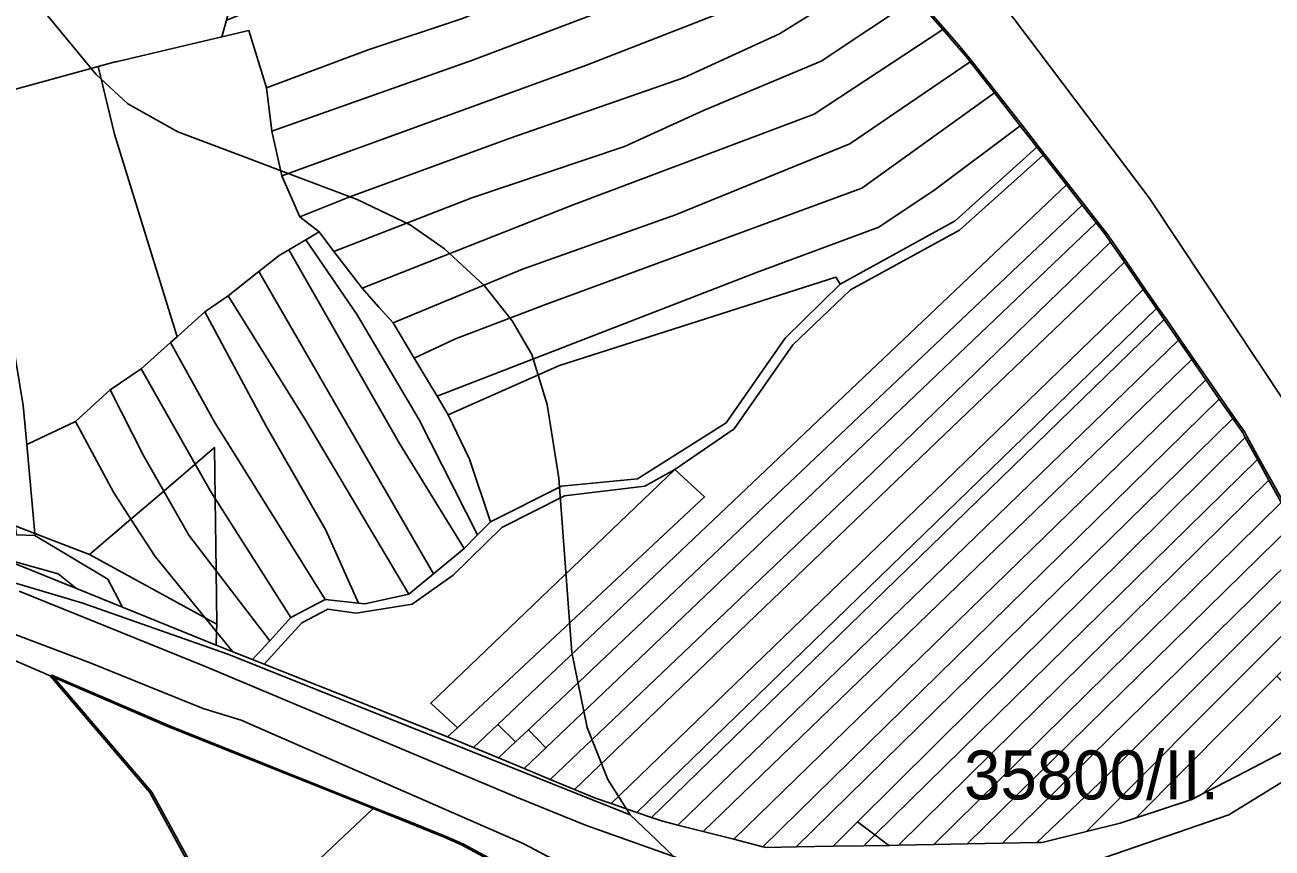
# Model space of a CAD drawing. Extents: x -535894 to -532827, y -1165802 to -1163635.
# Drawn here: x -533561 to -533178.9, y -1164904.6 to -1164652.6 of the extents above; entities that cross this region are included whole.
import ezdxf

# ---------------------------------------------------------------- set-up
doc = ezdxf.new("R2010")
doc.units = 0
for name, color, linetype in [('BPEJ_s', 7, 'Continuous'), ('orna_s', 7, 'Continuous'), ('ostatni_s', 7, 'Continuous'), ('PUPFL_s', 7, 'Continuous'), ('sad_s', 7, 'Continuous'), ('voda_s', 7, 'Continuous')]:
    doc.layers.add(name, color=color, linetype=linetype)

msp = doc.modelspace()

# ---------------------------------------------------------------- linework, layer by layer
at = {"layer": 'BPEJ_s'}
for points in [[(-533420.14, -1164732.49), (-533432.41, -1164721.18), (-533442.921, -1164713.859), (-533459.171, -1164706.05), (-533481.15, -1164697.769), (-533495.14, -1164692.5), (-533497.619, -1164691.566), (-533514.087, -1164685.362), (-533529.464, -1164676.803), (-533539.13, -1164667.83), (-533562.86, -1164639), (-533582.853, -1164607.463), (-533591.21, -1164585.32), (-533601.72, -1164540.56), (-533606.34, -1164507.75), (-533606.98, -1164481.63)], [(-533562.86, -1164639), (-533539.13, -1164667.83), (-533529.464, -1164676.803), (-533514.087, -1164685.362), (-533497.619, -1164691.566), (-533495.14, -1164692.5), (-533481.15, -1164697.769), (-533459.171, -1164706.05), (-533442.921, -1164713.859), (-533432.41, -1164721.18), (-533420.14, -1164732.49), (-533411.7, -1164743.171), (-533405.65, -1164753.52), (-533401.03, -1164768.81), (-533397.377, -1164791.431), (-533395.133, -1164821.465), (-533393.39, -1164844.791), (-533388.77, -1164867.72), (-533382.4, -1164883.65), (-533375.59, -1164894.45), (-533394.048, -1164887.08), (-533403.749, -1164883.207), (-533424.899, -1164874.762), (-533457.69, -1164861.67), (-533467.869, -1164857.606), (-533498.791, -1164845.26), (-533540.07, -1164830.759), (-533543.229, -1164829.65), (-533582.452, -1164818)], [(-533287.544, -1164644.206), (-533279.194, -1164653.887), (-533275.013, -1164658.729), (-533272.072, -1164662.135), (-533270.5, -1164664.24), (-533263.368, -1164673.254), (-533255.52, -1164683.292), (-533250.35, -1164689.904), (-533248.429, -1164692.351), (-533241.312, -1164701.443), (-533236.475, -1164707.625), (-533232.221, -1164713.068), (-533229.587, -1164716.44), (-533227.835, -1164718.959), (-533223.56, -1164725.119), (-533217.768, -1164733.469), (-533213.763, -1164739.247), (-533211.404, -1164742.648), (-533206.99, -1164749.005), (-533202.897, -1164754.903), (-533198.613, -1164761.074), (-533194.476, -1164767.027), (-533190.332, -1164773.001), (-533187.314, -1164777.351), (-533186.536, -1164778.766), (-533182.834, -1164785.465), (-533179.324, -1164791.812), (-533175.539, -1164798.672)], [(-533186.536, -1164778.766), (-533187.314, -1164777.351), (-533190.332, -1164773.001), (-533194.476, -1164767.027), (-533198.613, -1164761.074), (-533202.897, -1164754.903), (-533206.99, -1164749.005), (-533211.404, -1164742.648), (-533213.763, -1164739.247), (-533217.768, -1164733.469), (-533223.56, -1164725.119), (-533227.835, -1164718.959), (-533229.587, -1164716.44), (-533232.221, -1164713.068), (-533236.475, -1164707.625), (-533241.312, -1164701.443), (-533248.429, -1164692.351), (-533250.35, -1164689.904), (-533255.52, -1164683.292), (-533263.368, -1164673.254), (-533270.5, -1164664.24), (-533272.072, -1164662.135), (-533275.013, -1164658.729), (-533279.194, -1164653.887), (-533287.544, -1164644.206)], [(-533356.59, -1164912.8), (-533367.42, -1164902.28), (-533375.59, -1164894.45), (-533382.4, -1164883.65), (-533388.77, -1164867.72), (-533393.39, -1164844.791), (-533395.133, -1164821.465), (-533397.377, -1164791.431), (-533401.03, -1164768.81), (-533405.65, -1164753.52), (-533411.7, -1164743.171), (-533420.14, -1164732.49)], [(-533175.539, -1164798.672), (-533179.324, -1164791.812), (-533182.834, -1164785.465), (-533186.536, -1164778.766)], [(-533582.452, -1164818), (-533543.229, -1164829.65), (-533540.07, -1164830.759), (-533498.791, -1164845.26), (-533467.869, -1164857.606), (-533457.69, -1164861.67), (-533424.899, -1164874.762), (-533403.749, -1164883.207), (-533394.048, -1164887.08), (-533375.59, -1164894.45)], [(-533382.308, -1164927.394), (-533426.603, -1164903.475), (-533431.702, -1164901.198), (-533444.833, -1164895.95), (-533453.712, -1164892.401), (-533516.384, -1164867.359), (-533552.673, -1164851.701), (-533522.095, -1164887.508), (-533497.114, -1164933.287)], [(-533497.114, -1164933.287), (-533522.095, -1164887.508), (-533552.673, -1164851.701), (-533516.384, -1164867.359), (-533453.712, -1164892.401), (-533444.833, -1164895.95), (-533431.702, -1164901.198), (-533426.603, -1164903.475), (-533382.308, -1164927.394)], [(-533375.59, -1164894.45), (-533367.42, -1164902.28), (-533356.59, -1164912.8)]]:
    msp.add_lwpolyline(points, dxfattribs=at)
at = {"layer": 'orna_s'}
for points in [[(-533340.54, -1164585.66), (-533339.13, -1164587.05), (-533322.44, -1164605.61), (-533347.58, -1164619.33), (-533427.18, -1164650.69), (-533455.83, -1164660.22), (-533487.01, -1164671.82), (-533492.36, -1164654.31), (-533500.62, -1164656.25), (-533499.25, -1164651.17), (-533494.36, -1164649.22), (-533406.4, -1164614.18), (-533358.81, -1164596.53)], [(-533322.44, -1164605.61), (-533313.54, -1164615.51), (-533338.15, -1164629.18), (-533377.68, -1164645.97), (-533423.57, -1164663.33), (-533485.32, -1164685.09), (-533487.01, -1164671.82), (-533455.83, -1164660.22), (-533427.18, -1164650.69), (-533347.58, -1164619.33)], [(-533313.54, -1164615.51), (-533304.78, -1164625.25), (-533334.44, -1164643.61), (-533388.98, -1164664.88), (-533482.26, -1164698.81), (-533485.32, -1164685.09), (-533423.57, -1164663.33), (-533377.68, -1164645.97), (-533338.15, -1164629.18)], [(-533304.78, -1164625.25), (-533301.29, -1164629.13), (-533296.52, -1164634.66), (-533329.78, -1164655.32), (-533359.19, -1164668.82), (-533412.28, -1164687.27), (-533461.47, -1164705.24), (-533476.71, -1164711.39), (-533482.26, -1164698.81), (-533388.98, -1164664.88), (-533334.44, -1164643.61)], [(-533288.14, -1164644.37), (-533317.08, -1164663.67), (-533353.14, -1164678.82), (-533377.32, -1164689.81), (-533424.1, -1164705.54), (-533466.29, -1164721.94), (-533470.86, -1164715.95), (-533476.71, -1164711.39), (-533461.47, -1164705.24), (-533412.28, -1164687.27), (-533359.19, -1164668.82), (-533329.78, -1164655.32), (-533296.52, -1164634.66)], [(-533279.79, -1164654.05), (-533319.2, -1164679.92), (-533393, -1164707.69), (-533457.69, -1164733.24), (-533466.29, -1164721.94), (-533424.1, -1164705.54), (-533377.32, -1164689.81), (-533353.14, -1164678.82), (-533317.08, -1164663.67), (-533288.14, -1164644.37)], [(-533492.36, -1164654.31), (-533487.01, -1164671.82), (-533485.32, -1164685.09), (-533482.26, -1164698.81), (-533476.71, -1164711.39), (-533470.86, -1164715.95), (-533474.96, -1164718.4), (-533480.08, -1164721.45), (-533483.04, -1164723.22), (-533489.28, -1164728.14), (-533498.69, -1164735.57), (-533505.89, -1164740.44), (-533510.96, -1164745.02), (-533514.36, -1164748.08), (-533533.54, -1164686.07), (-533538.54, -1164665.37), (-533533.28, -1164663.93), (-533533.01, -1164663.86), (-533500.62, -1164656.25)], [(-533275.61, -1164658.9), (-533272.67, -1164662.3), (-533271.44, -1164663.87), (-533308.24, -1164688.97), (-533361.65, -1164710.75), (-533408.54, -1164727.43), (-533448.21, -1164743.81), (-533452.5, -1164739.03), (-533457.69, -1164733.24), (-533393, -1164707.69), (-533319.2, -1164679.92), (-533279.79, -1164654.05)], [(-533263.96, -1164673.42), (-533304.62, -1164702.63), (-533402.02, -1164738.38), (-533429.04, -1164748.7), (-533441.74, -1164754.6), (-533448.21, -1164743.81), (-533408.54, -1164727.43), (-533361.65, -1164710.75), (-533308.24, -1164688.97), (-533271.44, -1164663.87)], [(-533538.54, -1164665.37), (-533533.54, -1164686.07), (-533514.36, -1164748.08), (-533516.33, -1164749.86), (-533525.31, -1164757.95), (-533534.9, -1164764.3), (-533545.47, -1164773.99), (-533560.4, -1164781.07), (-533561.46, -1164769.12), (-533570.16, -1164717), (-533578.79, -1164676.38)], [(-533256.12, -1164683.46), (-533282.08, -1164703), (-533299.42, -1164714.57), (-533336.81, -1164728.38), (-533434.73, -1164766.3), (-533441.74, -1164754.6), (-533429.04, -1164748.7), (-533402.02, -1164738.38), (-533304.62, -1164702.63), (-533263.96, -1164673.42)], [(-533584.41, -1164677.93), (-533578.79, -1164676.38), (-533570.16, -1164717), (-533561.46, -1164769.12), (-533560.4, -1164781.07), (-533557.97, -1164808.32), (-533563.91, -1164806.02), (-533571.28, -1164756.52)], [(-533250.95, -1164690.07), (-533275.95, -1164712.64), (-533311.18, -1164731.99), (-533311.82, -1164730.97), (-533312.53, -1164729.81), (-533397.17, -1164756.86), (-533431.33, -1164771.97), (-533434.73, -1164766.3), (-533336.81, -1164728.38), (-533299.42, -1164714.57), (-533282.08, -1164703), (-533256.12, -1164683.46)], [(-533249.02, -1164692.52), (-533274.65, -1164715.44), (-533308.05, -1164733.69), (-533325.72, -1164750.58), (-533343.74, -1164776.33), (-533361.85, -1164788.7), (-533371.03, -1164793.86), (-533395.69, -1164796.81), (-533414.89, -1164806.5), (-533429.78, -1164821.14), (-533442.29, -1164829.96), (-533459.47, -1164832.75), (-533468.18, -1164831.46), (-533476.1, -1164835.72), (-533487.68, -1164848.33), (-533491.23, -1164846.91), (-533485.98, -1164841.17), (-533479.52, -1164834.02), (-533469.04, -1164828.56), (-533458.74, -1164829.65), (-533456.82, -1164829.86), (-533443.36, -1164826.95), (-533435.81, -1164820.69), (-533426.45, -1164812.95), (-533422.33, -1164808.76), (-533418.38, -1164804.75), (-533396.57, -1164793.83), (-533373.28, -1164791.61), (-533346.13, -1164774.47), (-533328.04, -1164748.55), (-533311.18, -1164731.99), (-533275.95, -1164712.64), (-533250.95, -1164690.07)], [(-533249.02, -1164692.52), (-533241.91, -1164701.61), (-533416.06, -1164866.8), (-533423.51, -1164873.88), (-533428.43, -1164871.84), (-533431.47, -1164870.62), (-533428.45, -1164867.8), (-533352.76, -1164797.14), (-533361.85, -1164788.7), (-533343.74, -1164776.33), (-533325.72, -1164750.58), (-533308.05, -1164733.69), (-533274.65, -1164715.44)], [(-533237.07, -1164707.79), (-533406.74, -1164868.43), (-533410.69, -1164872.17), (-533416.06, -1164866.8), (-533241.91, -1164701.61)], [(-533232.82, -1164713.23), (-533401.39, -1164873.99), (-533406.74, -1164868.43), (-533237.07, -1164707.79)], [(-533230.18, -1164716.6), (-533228.43, -1164719.12), (-533301.21, -1164789.57), (-533400.11, -1164883.63), (-533408.04, -1164880.32), (-533401.39, -1164873.99), (-533232.82, -1164713.23)], [(-533470.86, -1164715.95), (-533466.29, -1164721.94), (-533457.69, -1164733.24), (-533452.5, -1164739.03), (-533448.21, -1164743.81), (-533441.74, -1164754.6), (-533434.73, -1164766.3), (-533431.33, -1164771.97), (-533424.81, -1164785.55), (-533418.38, -1164804.75), (-533422.33, -1164808.76), (-533440.21, -1164773.49), (-533459.21, -1164741.38), (-533474.96, -1164718.4)], [(-533480.08, -1164721.45), (-533446.26, -1164780.81), (-533426.45, -1164812.95), (-533435.81, -1164820.69), (-533489.28, -1164728.14), (-533483.04, -1164723.22)], [(-533474.96, -1164718.4), (-533459.21, -1164741.38), (-533440.21, -1164773.49), (-533422.33, -1164808.76), (-533426.45, -1164812.95), (-533446.26, -1164780.81), (-533480.08, -1164721.45)], [(-533224.16, -1164725.28), (-533286.57, -1164785.1), (-533392.63, -1164886.74), (-533400.11, -1164883.63), (-533301.21, -1164789.57), (-533228.43, -1164719.12)], [(-533218.37, -1164733.63), (-533279.2, -1164792.37), (-533381.38, -1164891.04), (-533386.52, -1164889.28), (-533392.63, -1164886.74), (-533286.57, -1164785.1), (-533224.16, -1164725.28)], [(-533489.28, -1164728.14), (-533435.81, -1164820.69), (-533443.36, -1164826.95), (-533474.92, -1164773.7), (-533498.69, -1164735.57)], [(-533311.82, -1164730.97), (-533311.18, -1164731.99), (-533328.04, -1164748.55), (-533346.13, -1164774.47), (-533373.28, -1164791.61), (-533396.57, -1164793.83), (-533418.38, -1164804.75), (-533424.81, -1164785.55), (-533431.33, -1164771.97), (-533397.17, -1164756.86), (-533312.53, -1164729.81)], [(-533498.69, -1164735.57), (-533474.92, -1164773.7), (-533443.36, -1164826.95), (-533456.82, -1164829.86), (-533458.74, -1164829.65), (-533468.79, -1164807.32), (-533487.2, -1164775.28), (-533505.89, -1164740.44)], [(-533214.36, -1164739.41), (-533373.49, -1164893.74), (-533381.38, -1164891.04), (-533279.2, -1164792.37), (-533218.37, -1164733.63)], [(-533505.89, -1164740.44), (-533487.2, -1164775.28), (-533468.79, -1164807.32), (-533458.74, -1164829.65), (-533469.04, -1164828.56), (-533497.51, -1164782.8), (-533502.66, -1164774.54), (-533516.33, -1164749.86), (-533514.36, -1164748.08), (-533510.96, -1164745.02)], [(-533212, -1164742.81), (-533369.05, -1164895.26), (-533373.49, -1164893.74), (-533214.36, -1164739.41)], [(-533207.59, -1164749.17), (-533360.93, -1164897.6), (-533365.96, -1164896.32), (-533369.05, -1164895.26), (-533212, -1164742.81)], [(-533516.33, -1164749.86), (-533502.66, -1164774.54), (-533497.51, -1164782.8), (-533469.04, -1164828.56), (-533479.52, -1164834.02), (-533502.68, -1164797.66), (-533502.89, -1164782), (-533508.81, -1164787.07), (-533525.31, -1164757.95)], [(-533203.5, -1164755.07), (-533353.15, -1164899.58), (-533360.93, -1164897.6), (-533207.59, -1164749.17)], [(-533199.21, -1164761.24), (-533343.76, -1164901.98), (-533353.15, -1164899.58), (-533203.5, -1164755.07)], [(-533525.31, -1164757.95), (-533508.81, -1164787.07), (-533518.46, -1164795.33), (-533524.53, -1164784.7), (-533534.9, -1164764.3)], [(-533195.08, -1164767.19), (-533334.89, -1164904.23), (-533343.76, -1164901.98), (-533199.21, -1164761.24)], [(-533534.9, -1164764.3), (-533524.53, -1164784.7), (-533518.46, -1164795.33), (-533528.49, -1164803.93), (-533533.83, -1164795.72), (-533545.47, -1164773.99)], [(-533190.93, -1164773.16), (-533324.7, -1164904.32), (-533333.91, -1164904.48), (-533334.89, -1164904.23), (-533195.08, -1164767.19)], [(-533545.47, -1164773.99), (-533533.83, -1164795.72), (-533528.49, -1164803.93), (-533541.19, -1164814.8), (-533557.97, -1164808.32), (-533560.4, -1164781.07)], [(-533187.91, -1164777.51), (-533187.14, -1164778.93), (-533305.88, -1164896.66), (-533313.39, -1164904.12), (-533324.7, -1164904.32), (-533190.93, -1164773.16)], [(-533183.43, -1164785.63), (-533300.56, -1164900.63), (-533305.88, -1164896.66), (-533187.14, -1164778.93)], [(-533179.93, -1164791.97), (-533293.4, -1164903.76), (-533296.3, -1164903.82), (-533300.56, -1164900.63), (-533183.43, -1164785.63)], [(-533371.03, -1164793.86), (-533361.85, -1164788.7), (-533436.64, -1164860.32), (-533428.45, -1164867.8), (-533431.47, -1164870.62), (-533487.68, -1164848.33), (-533476.1, -1164835.72), (-533468.18, -1164831.46), (-533459.47, -1164832.75), (-533442.29, -1164829.96), (-533429.78, -1164821.14), (-533414.89, -1164806.5), (-533395.69, -1164796.81)], [(-533361.85, -1164788.7), (-533352.76, -1164797.14), (-533428.45, -1164867.8), (-533436.64, -1164860.32)], [(-533176.14, -1164798.83), (-533282.57, -1164903.56), (-533293.4, -1164903.76), (-533179.93, -1164791.97)], [(-533502.68, -1164797.66), (-533479.52, -1164834.02), (-533485.98, -1164841.17), (-533502.38, -1164819.76)], [(-533172.45, -1164805.52), (-533272.33, -1164903.38), (-533282.57, -1164903.56), (-533176.14, -1164798.83)], [(-533168.77, -1164812.17), (-533261.52, -1164903.19), (-533272.33, -1164903.38), (-533172.45, -1164805.52)], [(-533165.34, -1164818.38), (-533229.86, -1164882.85), (-533251.03, -1164902.99), (-533261.52, -1164903.19), (-533168.77, -1164812.17)], [(-533502.38, -1164819.76), (-533485.98, -1164841.17), (-533491.23, -1164846.91), (-533497.24, -1164844.53), (-533502.24, -1164838.41), (-533502.15, -1164836.07)], [(-533163.04, -1164822.52), (-533161.85, -1164825.47), (-533182.9, -1164846.57), (-533235.8, -1164899.62), (-533249.36, -1164902.96), (-533251.03, -1164902.99), (-533229.86, -1164882.85), (-533165.34, -1164818.38)], [(-533158.74, -1164833.17), (-533177.43, -1164852), (-533220.52, -1164895.43), (-533225.42, -1164897.07), (-533235.8, -1164899.62), (-533182.9, -1164846.57), (-533161.85, -1164825.47)], [(-533502.24, -1164838.41), (-533497.24, -1164844.53), (-533502.39, -1164842.48)], [(-533154.75, -1164843.06), (-533166.05, -1164860.58), (-533175.17, -1164875.08), (-533189.49, -1164882.49), (-533200, -1164887.93), (-533192.13, -1164880.06), (-533170.75, -1164858.64), (-533154.89, -1164842.74)], [(-533170.75, -1164858.64), (-533192.13, -1164880.06), (-533200, -1164887.93), (-533203.49, -1164889.74), (-533220.52, -1164895.43), (-533177.43, -1164852)], [(-533410.69, -1164872.17), (-533415.86, -1164877.07), (-533423.51, -1164873.88), (-533416.06, -1164866.8)], [(-533410.69, -1164872.17), (-533406.74, -1164868.43), (-533401.39, -1164873.99), (-533408.04, -1164880.32), (-533415.86, -1164877.07)], [(-533305.88, -1164896.66), (-533300.56, -1164900.63), (-533303.94, -1164903.95), (-533313.39, -1164904.12)], [(-533300.56, -1164900.63), (-533296.3, -1164903.82), (-533303.94, -1164903.95)]]:
    msp.add_lwpolyline(points, close=True, dxfattribs=at)
msp.add_lwpolyline([(-533589.15, -1164642.49), (-533534.45, -1164626.61), (-533502.26, -1164617.26), (-533500.35, -1164622.14), (-533495.05, -1164635.67), (-533499.25, -1164651.17), (-533500.62, -1164656.25), (-533533.01, -1164663.86), (-533533.28, -1164663.93), (-533538.54, -1164665.37), (-533578.79, -1164676.38)], dxfattribs=at)
at = {"layer": 'ostatni_s'}
for points in [[(-533404.17, -1164500.26), (-533365.03, -1164536.67), (-533325.21, -1164575.74), (-533286.88, -1164617.4), (-533258.18, -1164650.51), (-533216.56, -1164705.51), (-533174.44, -1164769.08)], [(-533176.14, -1164798.83), (-533179.93, -1164791.97), (-533183.43, -1164785.63), (-533187.14, -1164778.93), (-533187.91, -1164777.51), (-533190.93, -1164773.16), (-533195.08, -1164767.19), (-533199.21, -1164761.24), (-533203.5, -1164755.07), (-533207.59, -1164749.17), (-533212, -1164742.81), (-533214.36, -1164739.41), (-533218.37, -1164733.63), (-533224.16, -1164725.28), (-533228.43, -1164719.12), (-533230.18, -1164716.6), (-533232.82, -1164713.23), (-533237.07, -1164707.79), (-533241.91, -1164701.61), (-533249.02, -1164692.52), (-533250.95, -1164690.07), (-533256.12, -1164683.46), (-533263.96, -1164673.42), (-533271.44, -1164663.87), (-533272.67, -1164662.3), (-533275.61, -1164658.9), (-533279.79, -1164654.05), (-533288.14, -1164644.37)], [(-533562.74, -1164826), (-533505.42, -1164849.16), (-533410.4, -1164889.02), (-533389.23, -1164897.67), (-533361.33, -1164907.54)], [(-533391.45, -1164912.18), (-533408.38, -1164903.25), (-533494.69, -1164865.48), (-533506.09, -1164862.02), (-533509.4, -1164860.71), (-533541, -1164847.96), (-533589.21, -1164829.81)], [(-533589.21, -1164829.81), (-533541, -1164847.96), (-533509.4, -1164860.71), (-533506.09, -1164862.02), (-533494.69, -1164865.48), (-533408.38, -1164903.25), (-533391.45, -1164912.18)], [(-533369.34, -1164934.9), (-533427.21, -1164903.65), (-533432.31, -1164901.38), (-533454.32, -1164892.58), (-533516.99, -1164867.54), (-533553.28, -1164851.89), (-533596.46, -1164833.25)], [(-533236.41, -1164909.7), (-533192.2, -1164894.47), (-533171.4, -1164881.68), (-533146.9, -1164867.45), (-533132.1, -1164861.81), (-533130.26, -1164863.56), (-533127.47, -1164863.11), (-533123.98, -1164868.64), (-533119.52, -1164875.7), (-533116.52, -1164880.45), (-533127.62, -1164885.63), (-533134.02, -1164888.62), (-533147.32, -1164895.13), (-533230.7, -1164935.9)], [(-533497.72, -1164933.47), (-533454.32, -1164892.58), (-533432.31, -1164901.38), (-533427.21, -1164903.65), (-533369.34, -1164934.9)]]:
    msp.add_lwpolyline(points, dxfattribs=at)
for points in [[(-533508.81, -1164787.07), (-533502.89, -1164782), (-533502.68, -1164797.66), (-533503.83, -1164795.85)], [(-533518.46, -1164795.33), (-533508.81, -1164787.07), (-533503.83, -1164795.85), (-533502.68, -1164797.66), (-533502.38, -1164819.76), (-533510.76, -1164808.8)], [(-533528.49, -1164803.93), (-533518.46, -1164795.33), (-533510.76, -1164808.8), (-533502.38, -1164819.76), (-533502.15, -1164836.07), (-533505.74, -1164834.11), (-533521.06, -1164815.37)], [(-533603.81, -1164805.24), (-533587.26, -1164802.74), (-533586.49, -1164807.8), (-533563.5, -1164808.77), (-533557.91, -1164808.96), (-533535.6, -1164822.31), (-533531.09, -1164830.9), (-533545.15, -1164825.22), (-533550.79, -1164820.73), (-533568.75, -1164815.7), (-533573.32, -1164813.85), (-533583.58, -1164811.64), (-533589.91, -1164813.28), (-533612.92, -1164811.5), (-533616.18, -1164810.49), (-533616.74, -1164806.99)], [(-533541.19, -1164814.8), (-533528.49, -1164803.93), (-533521.06, -1164815.37), (-533505.74, -1164834.11)], [(-533557.97, -1164808.32), (-533557.91, -1164808.96), (-533563.5, -1164808.77), (-533563.91, -1164806.02)], [(-533557.91, -1164808.96), (-533557.97, -1164808.32), (-533541.19, -1164814.8), (-533505.74, -1164834.11), (-533502.24, -1164838.41), (-533502.39, -1164842.48), (-533531.09, -1164830.9), (-533535.6, -1164822.31)], [(-533568.75, -1164815.7), (-533550.79, -1164820.73), (-533545.15, -1164825.22)], [(-533505.74, -1164834.11), (-533502.15, -1164836.07), (-533502.24, -1164838.41)]]:
    msp.add_lwpolyline(points, close=True, dxfattribs=at)
at = {"layer": 'PUPFL_s'}
msp.add_lwpolyline([(-533516.99, -1164867.54), (-533454.32, -1164892.58), (-533497.72, -1164933.47), (-533522.7, -1164887.69), (-533553.28, -1164851.89)], close=True, dxfattribs=at)
at = {"layer": 'sad_s'}
msp.add_lwpolyline([(-533596.46, -1164833.25), (-533553.28, -1164851.89), (-533522.7, -1164887.69), (-533497.72, -1164933.47), (-533391.12, -1165001.26), (-533381.33, -1164991.55), (-533372.98, -1165023.48), (-533364.81, -1165056.97), (-533353.28, -1165054.53), (-533343.29, -1165052.42), (-533340.42, -1165060.46), (-533373.45, -1165068.48), (-533390.5, -1165066.09), (-533436.96, -1165021.83), (-533455.65, -1165016.42), (-533510.43, -1165042.58), (-533561.35, -1165072.56)], dxfattribs=at)
at = {"layer": 'voda_s'}
for points in [[(-533174.44, -1164769.08), (-533216.56, -1164705.51), (-533258.18, -1164650.51), (-533286.88, -1164617.4), (-533325.21, -1164575.74), (-533365.03, -1164536.67), (-533404.17, -1164500.26)], [(-533568.75, -1164815.7), (-533545.15, -1164825.22), (-533531.09, -1164830.9), (-533502.39, -1164842.48), (-533497.24, -1164844.53), (-533491.23, -1164846.91), (-533487.68, -1164848.33), (-533431.47, -1164870.62), (-533428.43, -1164871.84), (-533423.51, -1164873.88), (-533415.86, -1164877.07), (-533408.04, -1164880.32), (-533400.11, -1164883.63), (-533392.63, -1164886.74), (-533386.52, -1164889.28), (-533381.38, -1164891.04), (-533373.49, -1164893.74), (-533369.05, -1164895.26), (-533365.96, -1164896.32), (-533360.93, -1164897.6), (-533353.15, -1164899.58), (-533343.76, -1164901.98), (-533334.89, -1164904.23), (-533333.91, -1164904.48), (-533324.7, -1164904.32), (-533313.39, -1164904.12), (-533303.94, -1164903.95), (-533296.3, -1164903.82), (-533293.4, -1164903.76), (-533282.57, -1164903.56), (-533272.33, -1164903.38), (-533261.52, -1164903.19), (-533251.03, -1164902.99), (-533249.36, -1164902.96), (-533235.8, -1164899.62), (-533225.42, -1164897.07), (-533220.52, -1164895.43), (-533203.49, -1164889.74), (-533200, -1164887.93), (-533189.49, -1164882.49), (-533175.17, -1164875.08)], [(-533361.33, -1164907.54), (-533389.23, -1164897.67), (-533410.4, -1164889.02), (-533505.42, -1164849.16), (-533562.74, -1164826)], [(-533171.4, -1164881.68), (-533192.2, -1164894.47), (-533236.41, -1164909.7)]]:
    msp.add_lwpolyline(points, dxfattribs=at)

# ---------------------------------------------------------------- texts
at = {"layer": 'BPEJ_s'}
msp.add_text('35800/II.', height=15, dxfattribs=at).set_placement((-533273.29, -1164889.776))

doc.saveas('drawing.dxf')
